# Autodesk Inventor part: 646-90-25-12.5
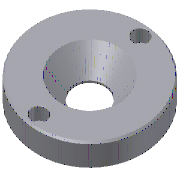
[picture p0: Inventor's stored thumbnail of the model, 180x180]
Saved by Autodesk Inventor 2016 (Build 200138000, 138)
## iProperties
IsCustomPart: 1
Created: 2015-02
Part Number: 646-90-25-12.5
Material: ANFOR XC 38 TS
Description: Locating Ring
Document SubType Name: Modeling
Designer: Sandeep
Standard Revision: 1
Manufacturer: RABOURDIN
Language: en-US
Size Designation: 646-90-25-12.5
Categories: <MemberInstance><Categories><Category DisplayName="Mold" InternalName="349578f2-f4d4-4954-8c09-8e99297a61c0" Mnemonic="MOLD"><Category DisplayName="Locatings" I
Density: 7.845 g/cm^3
Appearance: Default
Author: Sandeep
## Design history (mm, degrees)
sketch "Sketch1"
  geometry: L1 (0, -2.5)-(0, 15) reference; L2 (24, 12.5)-(12.5, 1); L3 (12.5, 1)-(12.5, 0); L4 (12.5, 0)-(45, 0); L5 (45, 0)-(45, 12.5); L6 (45, 12.5)-(24, 12.5); 1 further point
  constraints: 10 end point, 2 horizontal, 2 vertical, 1 point on line
  dimensions: "d0" = 45 deg angle of L1 L2; "d1" = 25 diameter of L3 L1 (= D2); "d2" = 90 diameter of L5 L1 (= D1); "d3" = 12.5 distance between parallel lines of L4 L6 (= A_); "d4" = 1 distance from line of L2.end L4 (= C_)
revolve "Revolution1" sketch "Sketch1" stored, may be unused: angle "d5" = 90 deg
sketch "Sketch2"
  geometry: 3 further points
  constraints: 2 vertical alignment
  dimensions: "d29" = 37 distance of point (0, 0) point (0, 37); "d30" = 37 distance of point (0, -37) point (0, 0)
hole "Hole1" sketch "Sketch2" diameter "d7" = 7; stored, may be unused: countersink angle "d11" = 90 deg, drill point angle "d13" = 0 deg; dims "d8" = 6, "d9" = 11, "d10" = 7, "d12" = 12.5 (= A_)
hole "Hole2" sketch "Sketch2" diameter "d31" = 7; stored, may be unused: countersink angle "d35" = 90 deg, drill point angle "d37" = 0 deg; dims "d32" = 6, "d33" = 11, "d34" = 7, "d36" = 12.5 (= A_)
chamfer "Chamfer1" distance "d14" = 1; stored, may be unused: second distance "d15" = 2, angle "d16" = 45 deg
chamfer "Chamfer2" distance "d17" = 0.5; stored, may be unused: second distance "d18" = 2, angle "d19" = 45 deg
chamfer "Chamfer3" distance "d20" = 0.3; stored, may be unused: second distance "d21" = 2, angle "d22" = 45 deg
sketch "Sketch3"
  geometry: L1 (0, -2.5)-(0, 15) reference; L2 (0, 0)-(45, 0); L3 (45, 0)-(45, 12.5); L4 (45, 12.5)-(0, 12.5); L5 (0, 12.5)-(0, 0)
  constraints: 8 end point, 2 parallel, 1 horizontal, 1 perpendicular
  dimensions: "d23" = 90 diameter of L3 L1 (= D1_CS); "d24" = 12.5 distance between parallel lines of L2 L4 (= A_CS)
feature "RevolutionSrf1" sketch "Sketch3" dims angle "d25" = 90 deg
body "Solid1"
body "Srf1"
other parameters: "D1" = 90 [user parameter; used in 1 equation term], "D2" = 25 [user parameter; used in 1 equation term], "A_" = 12.5 [user parameter; used in 3 equation terms], "C_" = 1 [user parameter; used in 1 equation term], "D1_CS" = 90 [user parameter; used in 1 equation term], "A_CS" = 12.5 [user parameter; used in 1 equation term], "d26" = 0, "d27" = 0, "d28" = 0
